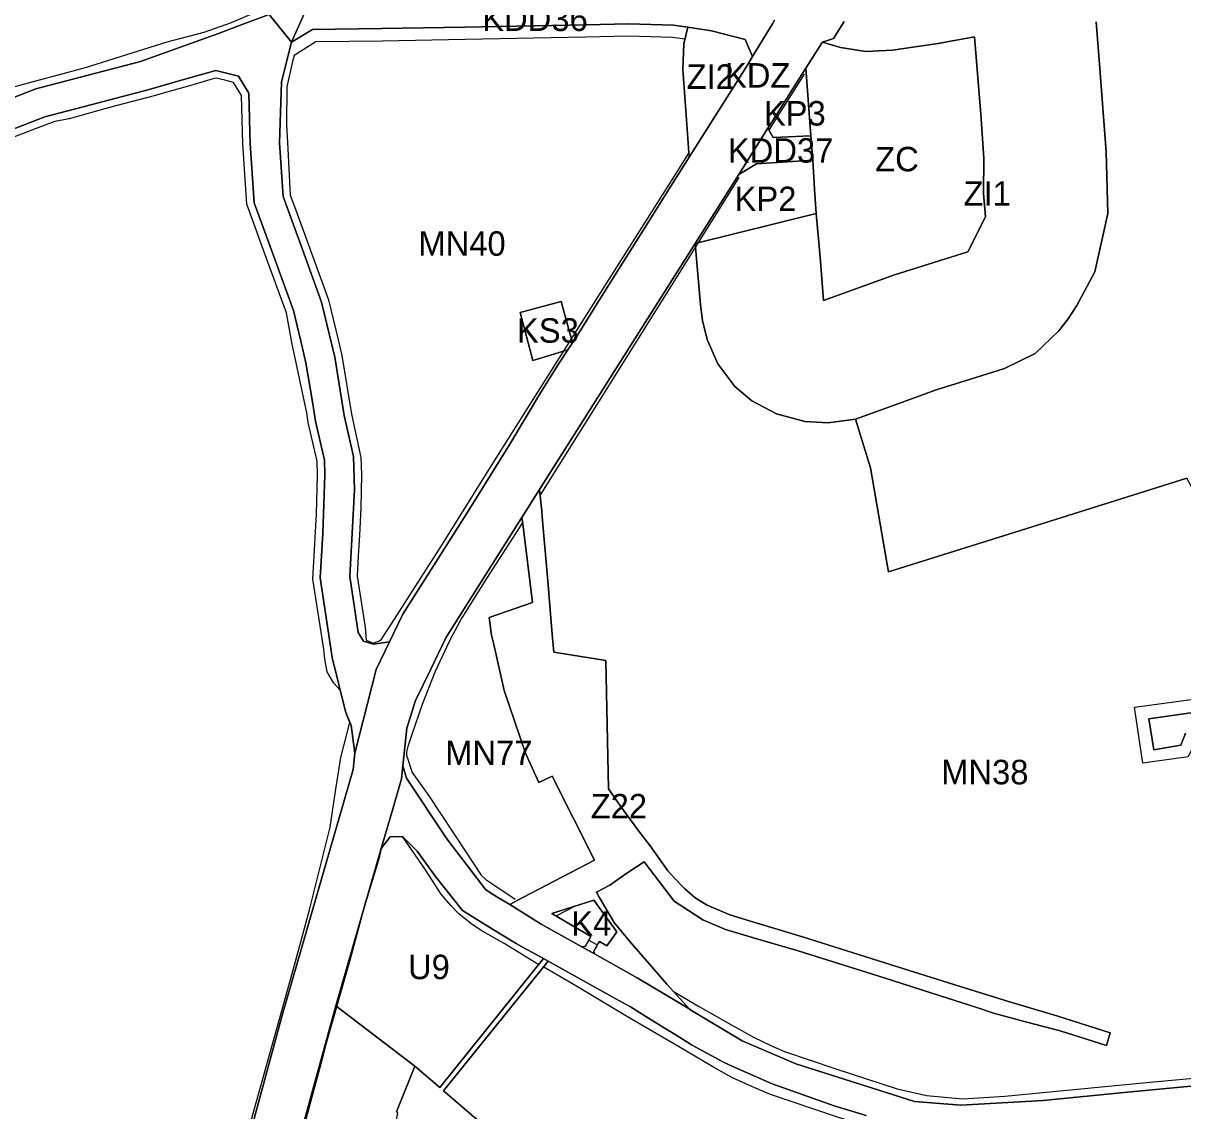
# Model space of a CAD drawing. Extents: x 7428841 to 7433518, y 5545054 to 5546840.
# Drawn here: x 7431482.5 to 7431956.4, y 5545561 to 5546005.4 of the extents above; entities that cross this region are included whole.
import ezdxf

# ---------------------------------------------------------------- set-up
doc = ezdxf.new("R2010")
doc.units = 0
for name, color, linetype in [('linie_rozgraniczajace', 7, 'Continuous'), ('linie_zabudowy_nieprzekraczalne', 7, 'Continuous'), ('oznaczenia_przeznaczen', 7, 'Continuous')]:
    doc.layers.add(name, color=color, linetype=linetype)

msp = doc.modelspace()

# ---------------------------------------------------------------- linework, layer by layer
at = {"layer": 'linie_rozgraniczajace'}
for points in [[(7431599.12, 5546013.1), (7431592.16, 5545997.56), (7431583, 5546008.93)], [(7431789.53, 5546006.64), (7431788.64, 5546005.06), (7431784.64, 5545998.46), (7431780.58, 5545991.74), (7431777.46, 5545998.73), (7431763.7, 5546002.28), (7431754.1, 5546003.7), (7431748.29, 5546004.56), (7431729.81, 5546005.04), (7431712.7, 5546004.67), (7431662.96, 5546003.76), (7431629.09, 5546003.17), (7431600.66, 5546002.77), (7431592.16, 5545997.56), (7431599.12, 5546013.1)], [(7431583, 5546008.93), (7431572.65, 5546005.07), (7431562.3, 5546001.22), (7431546.36, 5545995.5), (7431530.43, 5545989.77), (7431487.65, 5545978.49), (7431457.9, 5545966.94)], [(7431457.9, 5545966.94), (7431487.65, 5545978.49), (7431530.43, 5545989.77), (7431546.36, 5545995.5), (7431562.3, 5546001.22), (7431572.65, 5546005.07), (7431583, 5546008.93), (7431592.16, 5545997.56), (7431591.99, 5545997.19), (7431588.05, 5545981.31)], [(7431565.45, 5545515.61), (7431588.14, 5545599.59), (7431602.74, 5545650.06), (7431617.35, 5545700.53), (7431618.04, 5545707.09), (7431626.77, 5545741.31), (7431632.19, 5545752.61), (7431637.62, 5545763.91), (7431662.74, 5545803.43), (7431667.79, 5545811.49), (7431681.29, 5545833.44), (7431693.91, 5545854.36), (7431701.6, 5545866.73), (7431705.06, 5545871.95), (7431706.95, 5545874.78), (7431707.17, 5545875.1), (7431711.43, 5545881.87), (7431720.4, 5545896.3), (7431738.26, 5545924.58), (7431747.21, 5545938.73), (7431754.68, 5545950.57), (7431777.99, 5545987.46), (7431780.58, 5545991.74), (7431784.64, 5545998.46), (7431788.64, 5546005.06), (7431789.53, 5546006.64)], [(7431818, 5546006.01), (7431813.6, 5545999.06), (7431809.12, 5545997.63), (7431809.03, 5545997.46), (7431802.34, 5545986.99), (7431788.84, 5545965.65), (7431786.82, 5545962.45), (7431774.91, 5545943.61), (7431757.3, 5545915.76), (7431757.07, 5545915.39), (7431693.51, 5545814.87), (7431693.49, 5545814.84), (7431686.3, 5545803.47), (7431686.01, 5545803.02), (7431655.14, 5545754.2), (7431649, 5545741.4), (7431642.85, 5545728.6), (7431639.24, 5545717.39), (7431637.62, 5545702.03), (7431637.05, 5545696.67), (7431633.35, 5545683.9), (7431628.79, 5545668.13), (7431610.21, 5545603.92), (7431596.09, 5545552.33)], [(7431920.92, 5546005.95), (7431921.47, 5545998.98), (7431922.3, 5545988.6), (7431925.03, 5545952.86), (7431925.72, 5545927.64), (7431920.42, 5545903.85), (7431913.1, 5545889.98), (7431909.46, 5545884.59), (7431905.68, 5545879.64), (7431896.06, 5545870.46), (7431883.54, 5545864.27), (7431869.56, 5545859.9), (7431855.58, 5545855.53), (7431841.83, 5545850.56), (7431822.57, 5545843.63), (7431811.48, 5545842.12), (7431801.84, 5545842.63), (7431790.3, 5545845.74), (7431780.18, 5545851.1), (7431773.34, 5545856.88), (7431766.36, 5545866.23), (7431762.01, 5545876.1), (7431760.02, 5545883.84), (7431759.3, 5545890.24), (7431757.07, 5545915.39), (7431806.51, 5545927.6), (7431808.19, 5545909.81), (7431809.47, 5545892.04), (7431838.6, 5545902.55), (7431868.55, 5545911.97), (7431875.74, 5545926.28), (7431874.99, 5545935.78), (7431875.09, 5545950.22), (7431873.83, 5545968.21), (7431871.19, 5545999.76), (7431863.79, 5545998.44), (7431856.38, 5545997.13), (7431847.03, 5545995.76), (7431837.68, 5545994.39), (7431832.29, 5545994.07), (7431826.89, 5545993.76), (7431821.64, 5545994.62), (7431816.49, 5545995.45), (7431809.12, 5545997.63), (7431813.6, 5545999.06), (7431818, 5546006.01)], [(7431822.57, 5545843.63), (7431841.83, 5545850.56), (7431855.58, 5545855.53), (7431869.56, 5545859.9), (7431883.54, 5545864.27), (7431896.06, 5545870.46), (7431905.68, 5545879.64), (7431909.46, 5545884.59), (7431913.1, 5545889.98), (7431920.42, 5545903.85), (7431925.72, 5545927.64), (7431925.03, 5545952.86), (7431922.3, 5545988.6), (7431921.47, 5545998.98), (7431920.92, 5546005.95)], [(7431477.3, 5545961.6), (7431491.36, 5545967.06), (7431512.68, 5545972.68), (7431533.99, 5545978.31), (7431547.61, 5545982.16), (7431561.22, 5545986.02), (7431570.4, 5545983.79), (7431574.69, 5545976.77), (7431574.97, 5545966.52), (7431575.09, 5545960.7), (7431575.26, 5545956.28), (7431576.03, 5545944.15), (7431576.8, 5545932.01), (7431584.86, 5545909.99), (7431592.92, 5545887.96), (7431596.65, 5545872.55), (7431598.04, 5545866.6), (7431600.73, 5545850.66), (7431601.91, 5545842.83), (7431605.54, 5545826.82), (7431605.72, 5545820.86), (7431604.87, 5545796.82), (7431603.85, 5545778.74), (7431606.28, 5545762.51), (7431608.7, 5545746.29), (7431611.45, 5545735.24), (7431614.2, 5545724.19), (7431616.49, 5545718.47), (7431618.04, 5545707.09), (7431617.35, 5545700.53), (7431602.74, 5545650.06), (7431588.14, 5545599.59), (7431565.45, 5545515.61)], [(7431588.05, 5545981.31), (7431587.66, 5545968.89), (7431587.27, 5545956.47), (7431588.66, 5545934.51), (7431596.55, 5545912.97), (7431604.43, 5545891.43), (7431609.81, 5545868.97), (7431613.7, 5545845.12), (7431617.5, 5545828.34), (7431617.91, 5545814.74), (7431616.9, 5545797.02), (7431615.9, 5545779.29), (7431619.32, 5545756.44), (7431621.51, 5545752.87), (7431625.67, 5545751.71), (7431632.19, 5545752.61), (7431626.77, 5545741.31), (7431618.04, 5545707.09), (7431616.49, 5545718.47), (7431614.2, 5545724.19), (7431611.45, 5545735.24), (7431608.7, 5545746.29), (7431606.28, 5545762.51), (7431603.85, 5545778.74), (7431604.87, 5545796.82), (7431605.72, 5545820.86), (7431605.54, 5545826.82), (7431601.91, 5545842.83), (7431600.73, 5545850.66), (7431598.04, 5545866.6), (7431596.65, 5545872.55), (7431592.92, 5545887.96), (7431584.86, 5545909.99), (7431576.8, 5545932.01), (7431576.03, 5545944.15), (7431575.26, 5545956.28), (7431575.09, 5545960.7), (7431574.97, 5545966.52), (7431574.69, 5545976.77), (7431570.4, 5545983.79), (7431561.22, 5545986.02), (7431547.61, 5545982.16), (7431533.99, 5545978.31), (7431512.68, 5545972.68), (7431491.36, 5545967.06), (7431477.3, 5545961.6)], [(7431693.51, 5545814.87), (7431757.07, 5545915.39), (7431759.3, 5545890.24), (7431760.02, 5545883.84), (7431762.01, 5545876.1), (7431766.36, 5545866.23), (7431773.34, 5545856.88), (7431780.18, 5545851.1), (7431790.3, 5545845.74), (7431801.84, 5545842.63), (7431811.48, 5545842.12), (7431822.57, 5545843.63), (7431828.78, 5545823.75), (7431835.44, 5545785.08), (7431836.08, 5545781.23), (7431897.05, 5545800.35), (7431958.02, 5545819.48)], [(7431971.71, 5545794.23), (7431958.02, 5545819.48), (7431897.05, 5545800.35), (7431836.08, 5545781.23), (7431835.44, 5545785.08), (7431828.78, 5545823.75), (7431822.57, 5545843.63)], [(7431800.91, 5545632.12), (7431781.12, 5545638.13), (7431781.03, 5545638.16), (7431771.22, 5545641.13), (7431762.04, 5545644.99), (7431757.11, 5545648.04), (7431752.79, 5545651.87), (7431751.99, 5545652.57), (7431748.97, 5545655.82), (7431745.95, 5545659.08), (7431738.74, 5545669.22), (7431734.05, 5545675.24), (7431726.58, 5545685.49), (7431721.6, 5545692.59), (7431720.56, 5545745.02), (7431699.28, 5545748.43), (7431698.7, 5545755.62), (7431697.07, 5545775.9), (7431694.61, 5545803.72), (7431694.41, 5545806.09), (7431694.21, 5545808.46), (7431693.51, 5545814.87)], [(7432002.58, 5545729.76), (7431942.49, 5545721.23), (7431944.56, 5545708.52), (7431955.63, 5545710.38), (7431957.51, 5545715.35)], [(7431957.51, 5545715.35), (7431955.63, 5545710.38), (7431944.56, 5545708.52), (7431942.49, 5545721.23), (7432002.58, 5545729.76)], [(7431628.79, 5545668.13), (7431633.35, 5545683.9), (7431637.05, 5545696.67), (7431637.62, 5545702.03), (7431639.11, 5545696.87), (7431654.48, 5545673.76), (7431656.05, 5545671.59), (7431671.5, 5545651.29), (7431676.04, 5545648.46), (7431681.36, 5545645.27), (7431694.15, 5545637.22), (7431710.83, 5545627.97), (7431715.95, 5545625.13), (7431733.45, 5545615.42), (7431754.88, 5545602.49), (7431754.94, 5545602.45), (7431776.31, 5545589.56), (7431798.28, 5545580.23), (7431846.78, 5545564.82), (7431865.72, 5545563.35), (7431899.27, 5545565.29), (7431933.82, 5545568.58), (7431968.38, 5545571.86)], [(7431826.94, 5545559.07), (7431813.84, 5545563.02), (7431788.5, 5545572.07), (7431771.55, 5545579.6), (7431768.35, 5545581.02), (7431755.65, 5545588.01), (7431748.93, 5545592.17), (7431745.53, 5545594.28), (7431738.07, 5545598.9), (7431730.6, 5545603.52), (7431723.22, 5545607.61), (7431719.71, 5545609.55), (7431696.97, 5545622.15), (7431695.08, 5545623.19), (7431692.04, 5545624.88), (7431687.11, 5545627.61), (7431683.87, 5545629.43), (7431674.21, 5545635.29), (7431662.06, 5545642.88), (7431651.03, 5545656.79), (7431643.45, 5545667.1), (7431637.5, 5545673.08), (7431632.44, 5545672.91), (7431628.79, 5545668.13)], [(7431968.38, 5545571.86), (7431933.82, 5545568.58), (7431899.27, 5545565.29), (7431865.72, 5545563.35), (7431846.78, 5545564.82), (7431798.28, 5545580.23), (7431776.31, 5545589.56), (7431754.94, 5545602.45), (7431745.55, 5545612.71), (7431730.36, 5545630.24), (7431723.86, 5545638.1), (7431723.58, 5545638.59), (7431717.91, 5545648.37), (7431716.75, 5545650.37), (7431722.26, 5545653.2), (7431729.18, 5545658.18), (7431736.28, 5545662.73), (7431748.48, 5545646.73), (7431760.25, 5545639.06), (7431769.45, 5545635.07), (7431775.85, 5545633.2), (7431782.26, 5545631.33), (7431799.14, 5545626.41), (7431813.54, 5545621.94), (7431834.34, 5545615.39), (7431853.42, 5545609.23), (7431872.55, 5545603.05), (7431879.02, 5545600.96), (7431892.63, 5545597.3), (7431906.23, 5545593.64), (7431925.14, 5545587.75), (7431926.72, 5545592.91), (7431905.24, 5545599.76), (7431885.2, 5545605.66), (7431865.02, 5545611.91), (7431839.77, 5545619.82), (7431800.91, 5545632.12)], [(7431676.12, 5545550.46), (7431654.26, 5545569.14), (7431696.97, 5545622.15), (7431719.71, 5545609.55), (7431723.22, 5545607.61), (7431730.6, 5545603.52), (7431738.07, 5545598.9), (7431745.53, 5545594.28), (7431748.93, 5545592.17), (7431755.65, 5545588.01), (7431768.35, 5545581.02), (7431771.55, 5545579.6), (7431788.5, 5545572.07), (7431813.84, 5545563.02), (7431826.94, 5545559.07)], [(7431596.09, 5545552.33), (7431610.21, 5545603.92), (7431642.48, 5545579.21), (7431634.96, 5545560.58)]]:
    msp.add_lwpolyline(points, dxfattribs=at)
for points in [[(7431587.27, 5545956.47), (7431587.66, 5545968.89), (7431588.05, 5545981.31), (7431591.99, 5545997.19), (7431592.16, 5545997.56), (7431600.66, 5546002.77), (7431629.09, 5546003.17), (7431662.96, 5546003.76), (7431712.7, 5546004.67), (7431729.81, 5546005.04), (7431748.29, 5546004.56), (7431754.1, 5546003.7), (7431752.42, 5545996.97), (7431752.02, 5545986.44), (7431753.4, 5545967.82), (7431754.68, 5545950.57), (7431747.21, 5545938.73), (7431738.26, 5545924.58), (7431720.4, 5545896.3), (7431711.43, 5545881.87), (7431707.17, 5545875.1), (7431706.95, 5545874.78), (7431702.31, 5545891.7), (7431685.5, 5545887.15), (7431690.79, 5545867.63), (7431697.92, 5545869.79), (7431705.06, 5545871.95), (7431701.6, 5545866.73), (7431693.91, 5545854.36), (7431681.29, 5545833.44), (7431667.79, 5545811.49), (7431662.74, 5545803.43), (7431637.62, 5545763.91), (7431632.19, 5545752.61), (7431625.67, 5545751.71), (7431621.51, 5545752.87), (7431619.32, 5545756.44), (7431615.9, 5545779.29), (7431616.9, 5545797.02), (7431617.91, 5545814.74), (7431617.5, 5545828.34), (7431613.7, 5545845.12), (7431609.81, 5545868.97), (7431604.43, 5545891.43), (7431596.55, 5545912.97), (7431588.66, 5545934.51)], [(7431752.02, 5545986.44), (7431752.42, 5545996.97), (7431754.1, 5546003.7), (7431763.7, 5546002.28), (7431777.46, 5545998.73), (7431780.58, 5545991.74), (7431777.99, 5545987.46), (7431754.68, 5545950.57), (7431753.4, 5545967.82)], [(7431802.34, 5545986.99), (7431809.03, 5545997.46), (7431809.12, 5545997.63), (7431816.49, 5545995.45), (7431821.64, 5545994.62), (7431826.89, 5545993.76), (7431832.29, 5545994.07), (7431837.68, 5545994.39), (7431847.03, 5545995.76), (7431856.38, 5545997.13), (7431863.79, 5545998.44), (7431871.19, 5545999.76), (7431873.83, 5545968.21), (7431875.09, 5545950.22), (7431874.99, 5545935.78), (7431875.74, 5545926.28), (7431868.55, 5545911.97), (7431838.6, 5545902.55), (7431809.47, 5545892.04), (7431808.19, 5545909.81), (7431806.51, 5545927.6), (7431805.81, 5545937.56), (7431805.2, 5545949.35), (7431804.33, 5545959.32)], [(7431786.82, 5545962.45), (7431788.84, 5545965.65), (7431802.34, 5545986.99), (7431804.33, 5545959.32), (7431788.95, 5545958.7)], [(7431774.91, 5545943.61), (7431786.82, 5545962.45), (7431788.95, 5545958.7), (7431804.33, 5545959.32), (7431805.2, 5545949.35), (7431782.1, 5545947.9)], [(7431757.07, 5545915.39), (7431757.3, 5545915.76), (7431774.91, 5545943.61), (7431782.1, 5545947.9), (7431805.2, 5545949.35), (7431805.81, 5545937.56), (7431806.51, 5545927.6)], [(7431685.5, 5545887.15), (7431702.31, 5545891.7), (7431706.95, 5545874.78), (7431705.06, 5545871.95), (7431697.92, 5545869.79), (7431690.79, 5545867.63)], [(7431672.94, 5545762.63), (7431690.56, 5545768.71), (7431686.61, 5545800.81), (7431686.3, 5545803.47), (7431693.49, 5545814.84), (7431693.51, 5545814.87), (7431694.21, 5545808.46), (7431694.41, 5545806.09), (7431694.61, 5545803.72), (7431697.07, 5545775.9), (7431698.7, 5545755.62), (7431699.28, 5545748.43), (7431720.56, 5545745.02), (7431721.6, 5545692.59), (7431726.58, 5545685.49), (7431734.05, 5545675.24), (7431738.74, 5545669.22), (7431745.95, 5545659.08), (7431748.97, 5545655.82), (7431751.99, 5545652.57), (7431752.79, 5545651.87), (7431757.11, 5545648.04), (7431762.04, 5545644.99), (7431771.22, 5545641.13), (7431781.03, 5545638.16), (7431781.12, 5545638.13), (7431800.91, 5545632.12), (7431839.77, 5545619.82), (7431865.02, 5545611.91), (7431885.2, 5545605.66), (7431905.24, 5545599.76), (7431926.72, 5545592.91), (7431925.14, 5545587.75), (7431906.23, 5545593.64), (7431892.63, 5545597.3), (7431879.02, 5545600.96), (7431872.55, 5545603.05), (7431853.42, 5545609.23), (7431834.34, 5545615.39), (7431813.54, 5545621.94), (7431799.14, 5545626.41), (7431782.26, 5545631.33), (7431775.85, 5545633.2), (7431769.45, 5545635.07), (7431760.25, 5545639.06), (7431748.48, 5545646.73), (7431736.28, 5545662.73), (7431729.18, 5545658.18), (7431722.26, 5545653.2), (7431716.75, 5545650.37), (7431717.91, 5545648.37), (7431723.58, 5545638.59), (7431723.86, 5545638.1), (7431730.36, 5545630.24), (7431745.55, 5545612.71), (7431754.94, 5545602.45), (7431754.88, 5545602.49), (7431733.45, 5545615.42), (7431715.95, 5545625.13), (7431715.64, 5545626.3), (7431717.43, 5545629.33), (7431717.93, 5545630.17), (7431720.94, 5545628.39), (7431723.78, 5545632.37), (7431725.07, 5545634.18), (7431715.67, 5545647.11), (7431698.54, 5545641.59), (7431714.48, 5545632.21), (7431713.96, 5545631.33), (7431712.2, 5545628.33), (7431710.83, 5545627.97), (7431694.15, 5545637.22), (7431681.36, 5545645.27), (7431686.59, 5545648.15), (7431715.95, 5545663.43), (7431698.59, 5545697.68), (7431693.14, 5545695.15), (7431687.8, 5545707.11), (7431681.21, 5545726.4), (7431679.05, 5545732.68), (7431674.78, 5545751.56), (7431673.91, 5545755.39)], [(7431637.62, 5545702.03), (7431639.24, 5545717.39), (7431642.85, 5545728.6), (7431649, 5545741.4), (7431655.14, 5545754.2), (7431686.01, 5545803.02), (7431686.3, 5545803.47), (7431686.61, 5545800.81), (7431690.56, 5545768.71), (7431672.94, 5545762.63), (7431673.91, 5545755.39), (7431674.78, 5545751.56), (7431679.05, 5545732.68), (7431681.21, 5545726.4), (7431687.8, 5545707.11), (7431693.14, 5545695.15), (7431698.59, 5545697.68), (7431715.95, 5545663.43), (7431686.59, 5545648.15), (7431681.36, 5545645.27), (7431676.04, 5545648.46), (7431671.5, 5545651.29), (7431656.05, 5545671.59), (7431654.48, 5545673.76), (7431639.11, 5545696.87)], [(7431610.21, 5545603.92), (7431628.79, 5545668.13), (7431632.44, 5545672.91), (7431637.5, 5545673.08), (7431643.45, 5545667.1), (7431651.03, 5545656.79), (7431662.06, 5545642.88), (7431674.21, 5545635.29), (7431683.87, 5545629.43), (7431687.11, 5545627.61), (7431692.04, 5545624.88), (7431695.08, 5545623.19), (7431652.8, 5545570.54), (7431642.48, 5545579.21)], [(7431698.54, 5545641.59), (7431715.67, 5545647.11), (7431725.07, 5545634.18), (7431723.78, 5545632.37), (7431720.94, 5545628.39), (7431717.93, 5545630.17), (7431717.43, 5545629.33), (7431715.64, 5545626.3), (7431715.95, 5545625.13), (7431710.83, 5545627.97), (7431712.2, 5545628.33), (7431713.96, 5545631.33), (7431714.48, 5545632.21)], [(7431631.82, 5545527.07), (7431632.3, 5545540.87), (7431635.52, 5545560.38), (7431634.96, 5545560.58), (7431642.48, 5545579.21), (7431652.8, 5545570.54), (7431695.08, 5545623.19), (7431696.97, 5545622.15), (7431654.26, 5545569.14), (7431676.12, 5545550.46), (7431697.97, 5545531.78), (7431716.53, 5545515.45)]]:
    msp.add_lwpolyline(points, close=True, dxfattribs=at)
at = {"layer": 'linie_zabudowy_nieprzekraczalne'}
for points in [[(7431179.86, 5545828.51), (7431194.55, 5545832.95), (7431208.56, 5545838.51), (7431222.38, 5545847.36), (7431241, 5545860.79), (7431254.18, 5545867.16), (7431290.1, 5545877.07), (7431303.51, 5545880.27), (7431315.58, 5545884.55), (7431328.71, 5545890.98), (7431356.1, 5545909.93), (7431377.12, 5545923.45), (7431455.24, 5545969.15), (7431477.61, 5545979.11), (7431507.9, 5545987.31), (7431541.37, 5545997.7), (7431556.39, 5546001.76), (7431567.62, 5546005.71), (7431576.19, 5546009.27), (7431579.49, 5546011.06)], [(7431753.02, 5545998.88), (7431747.85, 5545999.57), (7431729.78, 5546000.04), (7431712.23, 5545999.68), (7431663.06, 5545998.76), (7431629.17, 5545998.09), (7431602.06, 5545997.73), (7431593.21, 5545992.11)], [(7431593.21, 5545992.11), (7431592.51, 5545989.76), (7431590.23, 5545979.35), (7431590.03, 5545964.01), (7431590.61, 5545953.99), (7431591.63, 5545935.13), (7431592.99, 5545931.57), (7431596.88, 5545920.86), (7431607.3, 5545892.31), (7431611.24, 5545876.03), (7431612.75, 5545869.57), (7431616.67, 5545845.69), (7431620.44, 5545827.93), (7431620.72, 5545820.82), (7431620.43, 5545807.5), (7431619.86, 5545796.13), (7431619.39, 5545787.78), (7431618.91, 5545779.43), (7431622.23, 5545758.57), (7431622.57, 5545753.3), (7431625.48, 5545752.14)], [(7431568.48, 5545981.17), (7431568.48, 5545981.17), (7431564.88, 5545982.04), (7431561.28, 5545982.92), (7431559.15, 5545982.38), (7431550.92, 5545979.93), (7431541.22, 5545977.22), (7431535.94, 5545975.65), (7431517.71, 5545970.9), (7431501.31, 5545966.36), (7431495.46, 5545965.2), (7431489.59, 5545962.96), (7431464.56, 5545953.43)], [(7431801.66, 5545984.6), (7431787.32, 5545961.93)], [(7431592.25, 5545874.93), (7431590.05, 5545887.09), (7431581.94, 5545909.24), (7431573.83, 5545931.39), (7431572.26, 5545956.12), (7431571.71, 5545975.89), (7431568.48, 5545981.17)], [(7431625.48, 5545752.14), (7431628.04, 5545753.08), (7431628.92, 5545753.69), (7431632.95, 5545759.99), (7431653.82, 5545792.5), (7431673.39, 5545823.93), (7431710.49, 5545882.62), (7431749.05, 5545943.58), (7431754.79, 5545952.7)], [(7431774.94, 5545942.34), (7431748.61, 5545900.29), (7431693.59, 5545812.38)], [(7431598.37, 5545846.23), (7431592.25, 5545874.93)], [(7431615.98, 5545719.72), (7431615.34, 5545721.33), (7431614.2, 5545724.19), (7431612.07, 5545732.86), (7431609.47, 5545735.73), (7431606.68, 5545740.41), (7431605.8, 5545745.58), (7431605.37, 5545749.63), (7431600.78, 5545778.24), (7431601.36, 5545787.78), (7431602.28, 5545804.94), (7431602.72, 5545820.86), (7431602.55, 5545826.44), (7431598.96, 5545842.28), (7431598.37, 5545846.23), (7431598.37, 5545846.23)], [(7431686.32, 5545801.05), (7431671.77, 5545778.5), (7431661.78, 5545762.4), (7431656.93, 5545753.54), (7431650.66, 5545740.21), (7431645.55, 5545726.99), (7431641.34, 5545714.79), (7431639.71, 5545709.83), (7431639.11, 5545707.68), (7431639.15, 5545706.38), (7431641.46, 5545699.2)], [(7431936.68, 5545725.89), (7432001.04, 5545734.59), (7432019.04, 5545743.9)], [(7431961.11, 5545710.93), (7431958.6, 5545705.65), (7431940.1, 5545703), (7431936.68, 5545725.89)], [(7431546.82, 5545448.63), (7431548.84, 5545455.82), (7431563.04, 5545512.38), (7431568.23, 5545530.64), (7431592.88, 5545619.09), (7431599.29, 5545642.6), (7431607.98, 5545676.87), (7431610.19, 5545692.41), (7431612.33, 5545705.4), (7431615.98, 5545719.72)], [(7431641.46, 5545699.2), (7431648.29, 5545689.71), (7431663.1, 5545667.26), (7431669.65, 5545657.28), (7431671.56, 5545655.51), (7431674.35, 5545653.59)], [(7431637.5, 5545673.08), (7431634.97, 5545673), (7431632.44, 5545672.91), (7431628.79, 5545668.13), (7431627.99, 5545664.43), (7431621.49, 5545643.25), (7431616.1, 5545622.96), (7431606.17, 5545588.13), (7431604.49, 5545581.76), (7431597.75, 5545556.46), (7431595.63, 5545548.68), (7431594, 5545541.71), (7431593.96, 5545541.56), (7431588.47, 5545523.55)], [(7431693.26, 5545620.71), (7431678.99, 5545629.34), (7431669.69, 5545634.76), (7431665.47, 5545637.55), (7431660.54, 5545641.52), (7431657.23, 5545644.94), (7431653.33, 5545649.59), (7431646.86, 5545659.42), (7431641.13, 5545667.79), (7431637.5, 5545673.08)], [(7431674.35, 5545653.59), (7431683.52, 5545647.54)], [(7431707.79, 5545644.44), (7431700.19, 5545640.54)], [(7431713.59, 5545630.73), (7431716.97, 5545628.84)], [(7431828.41, 5545554.27), (7431824.82, 5545555.48), (7431815.24, 5545558.5), (7431787.92, 5545567.63), (7431780.54, 5545570.78), (7431772.29, 5545574.5), (7431764.26, 5545579), (7431750.25, 5545587.35), (7431729.4, 5545599.47), (7431708.37, 5545612.07), (7431695.18, 5545619.71)], [(7431748.06, 5545609.87), (7431758.17, 5545603.9), (7431772.63, 5545595.72), (7431780.9, 5545591.16), (7431788.24, 5545587.54), (7431793.62, 5545585.27), (7431814.53, 5545578.23), (7431839.6, 5545570.04), (7431851.69, 5545567.23), (7431866.48, 5545565.87), (7431883.65, 5545567.05), (7431938.69, 5545572.35), (7431960.73, 5545574.4), (7431995.49, 5545578.54), (7432010.41, 5545581.02), (7432018.56, 5545582.74), (7432033.67, 5545586.14), (7432052.34, 5545591.47), (7432075.03, 5545599.16), (7432093.38, 5545605.62), (7432098.37, 5545607.65), (7432108.45, 5545612.2), (7432110.31, 5545613.14)]]:
    msp.add_lwpolyline(points, dxfattribs=at)

# ---------------------------------------------------------------- texts
at = {"layer": 'oznaczenia_przeznaczen'}
for s, p in [('KDD36', (7431670.07, 5546002.17)), ('ZI2', (7431753.58, 5545978.54)), ('KDZ', (7431769.27, 5545979.05)), ('KP3', (7431785.17, 5545963.55)), ('KDD37', (7431770.47, 5545948.39)), ('ZC', (7431830.65, 5545944.85)), ('ZI1', (7431866.76, 5545930.78)), ('KP2', (7431773.2, 5545928.59)), ('MN40', (7431643.97, 5545910.35)), ('KS3', (7431684.26, 5545874.83)), ('MN77', (7431654.94, 5545702.29)), ('MN38', (7431857.63, 5545694.42)), ('Z22', (7431714.39, 5545680.49)), ('K4', (7431706.48, 5545632.58)), ('U9', (7431639.73, 5545614.81))]:
    msp.add_text(s, height=10, dxfattribs=at).set_placement(p)

doc.saveas('drawing.dxf')
